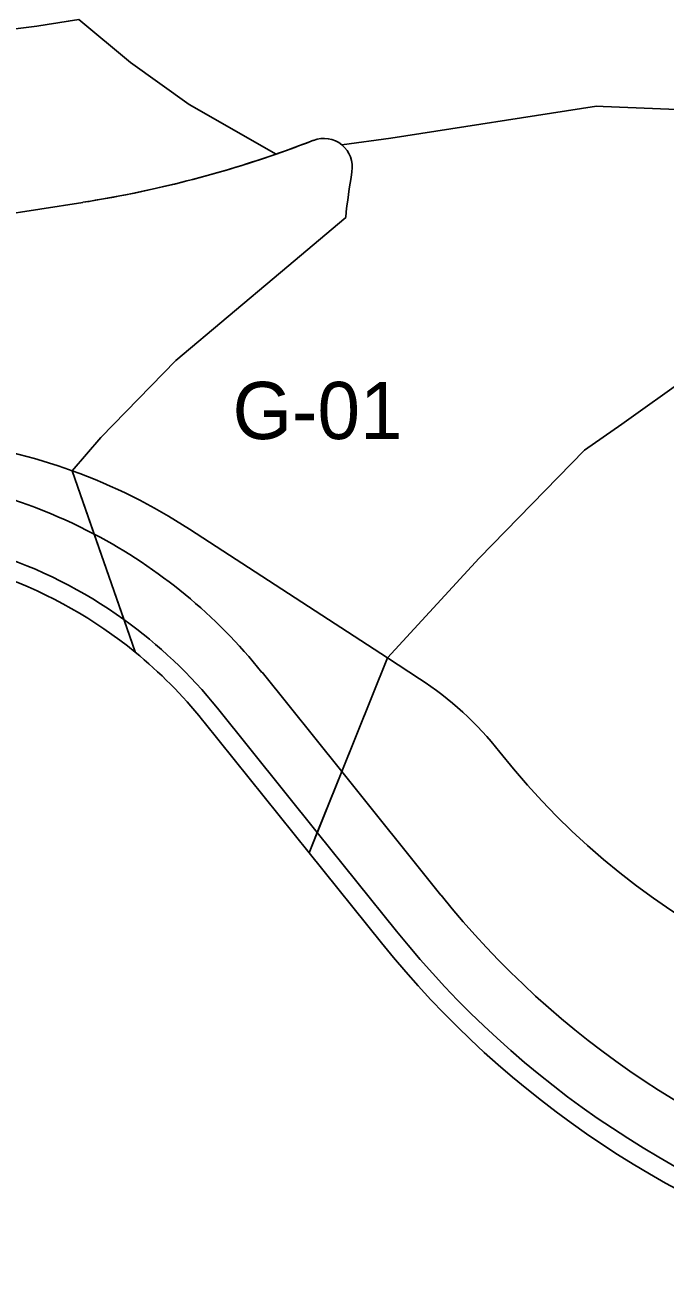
# Model space of a CAD drawing. Extents: x 5196716 to 5200291, y 3709146 to 3713154.
# Drawn here: x 5197340.6 to 5197407.8, y 3709241.5 to 3709372.1 of the extents above; entities that cross this region are included whole.
import ezdxf

# ---------------------------------------------------------------- set-up
doc = ezdxf.new("R2010")
doc.units = 0
for name, color, linetype in [('Drainage-Area', 7, 'Continuous'), ('dsnTextNote', 7, 'Continuous'), ('Level 1', 7, 'Continuous'), ('Level 2', 7, 'Continuous'), ('Level 4', 7, 'Continuous')]:
    doc.layers.add(name, color=color, linetype=linetype)

msp = doc.modelspace()

# ---------------------------------------------------------------- linework, layer by layer
at = {"layer": 'Drainage-Area'}
msp.add_lwpolyline([(5197366.96, 3709358.52), (5197357.83, 3709363.71), (5197351.66, 3709368.11), (5197346.24, 3709372.65)], dxfattribs=at)
at = {"layer": 'Level 1'}
for p, q in [((5197378.98, 3709360.18), (5197400.56, 3709363.54)), ((5197401.27, 3709363.5), (5197400.56, 3709363.54)), ((5197400.56, 3709363.54), (5197401.27, 3709363.5)), ((5197414.02, 3709363.01), (5197401.27, 3709363.5)), ((5197401.27, 3709363.5), (5197414.02, 3709363.01)), ((5197373.85, 3709359.48), (5197378.98, 3709360.18)), ((5197346.68, 3709353.45), (5197325, 3709350.07)), ((5197330.45, 3709350.92), (5197346.68, 3709353.45)), ((5197374.25, 3709351.87), (5197367.41, 3709346.1)), ((5197367.41, 3709346.1), (5197374.25, 3709351.87)), ((5197367.41, 3709346.1), (5197356.44, 3709336.84)), ((5197356.44, 3709336.84), (5197367.41, 3709346.1)), ((5197356.44, 3709336.84), (5197348.55, 3709328.76)), ((5197348.55, 3709328.76), (5197356.44, 3709336.84)), ((5197403.22, 3709330.19), (5197410.2, 3709335.15)), ((5197410.2, 3709335.15), (5197403.22, 3709330.19)), ((5197399.31, 3709327.43), (5197403.22, 3709330.19)), ((5197403.22, 3709330.19), (5197399.31, 3709327.43)), ((5197348.55, 3709328.76), (5197345.54, 3709325.29)), ((5197345.54, 3709325.29), (5197348.55, 3709328.76)), ((5197388.25, 3709316.13), (5197399.31, 3709327.43)), ((5197399.31, 3709327.43), (5197388.25, 3709316.13)), ((5197345.54, 3709325.29), (5197352.15, 3709306.27)), ((5197352.15, 3709306.27), (5197345.54, 3709325.29)), ((5197378.63, 3709305.65), (5197388.25, 3709316.13)), ((5197388.25, 3709316.13), (5197378.63, 3709305.65)), ((5197370.41, 3709285.21), (5197378.63, 3709305.65)), ((5197378.63, 3709305.65), (5197370.41, 3709285.21)), ((5197359.23, 3709299.13), (5197359.4, 3709298.92)), ((5197359.4, 3709298.92), (5197370.41, 3709285.21)), ((5197370.41, 3709285.21), (5197378.01, 3709275.74))]:
    msp.add_line(p, q, dxfattribs=at)
for points in [[(5197366.96, 3709358.52), (5197357.83, 3709363.71), (5197351.66, 3709368.11), (5197346.24, 3709372.65)], [(5197346.24, 3709372.65), (5197351.66, 3709368.11), (5197357.83, 3709363.71), (5197366.96, 3709358.52)], [(5197400.56, 3709363.54), (5197378.98, 3709360.18), (5197373.85, 3709359.48)]]:
    msp.add_lwpolyline(points, dxfattribs=at)
for centre, radius, start, end in [((5197328.7, 3709468.56), 116.5, 278.8769, 291.2212), ((5197328.7, 3709468.56), 116.5, 289.1719, 291.2212), ((5197371.95, 3709357.16), 3, 50.7986, 111.2212), ((5197371.95, 3709357.16), 3, 50.7986, 111.2212), ((5197371.95, 3709357.16), 3, 350.376, 50.7986), ((5197371.95, 3709357.16), 3, 350.376, 50.7986), ((5197328.7, 3709468.56), 116.5, 278.8769, 289.1719), ((5197451.32, 3709343.7), 77.5, 170.376, 173.947), ((5197451.32, 3709343.7), 77.5, 170.376, 173.947), ((5197321.8, 3709269.07), 48, 50.7893, 89.4347), ((5197321.8, 3709269.07), 48, 38.7641, 50.7893), ((5197457.55, 3709339.6), 102, 218.7641, 254.0813)]:
    msp.add_arc(centre, radius, start, end, dxfattribs=at)
at = {"layer": 'Level 2'}
for p, q in [((5197351.66, 3709368.11), (5197346.24, 3709372.65)), ((5197357.83, 3709363.71), (5197351.66, 3709368.11)), ((5197366.96, 3709358.52), (5197357.83, 3709363.71)), ((5197378.98, 3709360.18), (5197400.56, 3709363.54)), ((5197400.56, 3709363.54), (5197401.27, 3709363.5)), ((5197401.27, 3709363.5), (5197400.56, 3709363.54)), ((5197401.27, 3709363.5), (5197414.02, 3709363.01)), ((5197414.02, 3709363.01), (5197401.27, 3709363.5)), ((5197373.85, 3709359.48), (5197378.98, 3709360.18)), ((5197330.45, 3709350.92), (5197346.68, 3709353.45)), ((5197346.68, 3709353.45), (5197330.45, 3709350.92)), ((5197374.25, 3709351.87), (5197367.41, 3709346.1)), ((5197367.41, 3709346.1), (5197374.25, 3709351.87)), ((5197367.41, 3709346.1), (5197356.44, 3709336.84)), ((5197356.44, 3709336.84), (5197367.41, 3709346.1)), ((5197356.44, 3709336.84), (5197348.55, 3709328.76)), ((5197348.55, 3709328.76), (5197356.44, 3709336.84)), ((5197410.2, 3709335.15), (5197403.22, 3709330.19)), ((5197403.22, 3709330.19), (5197410.2, 3709335.15)), ((5197403.22, 3709330.19), (5197399.31, 3709327.43)), ((5197399.31, 3709327.43), (5197403.22, 3709330.19)), ((5197348.55, 3709328.76), (5197345.54, 3709325.29)), ((5197345.54, 3709325.29), (5197348.55, 3709328.76)), ((5197399.31, 3709327.43), (5197388.25, 3709316.13)), ((5197388.25, 3709316.13), (5197399.31, 3709327.43)), ((5197357.86, 3709319.16), (5197378.63, 3709305.65)), ((5197347.85, 3709318.65), (5197350.96, 3709309.7)), ((5197350.96, 3709309.7), (5197347.85, 3709318.65)), ((5197388.25, 3709316.13), (5197378.63, 3709305.65)), ((5197378.63, 3709305.65), (5197388.25, 3709316.13)), ((5197378.63, 3709305.65), (5197382.01, 3709303.45)), ((5197373.83, 3709293.72), (5197365.47, 3709304.14)), ((5197360.79, 3709300.38), (5197371.26, 3709287.34)), ((5197373.83, 3709293.72), (5197371.26, 3709287.34)), ((5197371.26, 3709287.34), (5197373.83, 3709293.72)), ((5197384.25, 3709280.74), (5197373.83, 3709293.72)), ((5197371.26, 3709287.34), (5197379.57, 3709276.99))]:
    msp.add_line(p, q, dxfattribs=at)
for points in [[(5197346.24, 3709372.65), (5197351.66, 3709368.11), (5197357.83, 3709363.71), (5197366.96, 3709358.52)], [(5197400.56, 3709363.54), (5197378.98, 3709360.18), (5197373.85, 3709359.48)]]:
    msp.add_lwpolyline(points, dxfattribs=at)
for centre, radius, start, end in [((5197328.7, 3709468.56), 97.5, 269.8354, 280.3656), ((5197328.7, 3709468.56), 116.5, 278.8769, 291.2212), ((5197328.7, 3709468.56), 116.5, 289.1719, 291.2212), ((5197371.95, 3709357.16), 3, 50.7986, 111.2212), ((5197371.95, 3709357.16), 3, 50.7986, 111.2212), ((5197371.95, 3709357.16), 3, 350.376, 50.7986), ((5197371.95, 3709357.16), 3, 350.376, 50.7986), ((5197328.7, 3709468.56), 116.5, 278.8769, 289.1719), ((5197451.32, 3709343.7), 77.5, 170.376, 173.947), ((5197451.32, 3709343.7), 77.5, 170.376, 173.947), ((5197325.15, 3709268.86), 60, 70.1272, 82.8549), ((5197321.8, 3709269.07), 56, 62.2868, 89.8345), ((5197325.15, 3709268.86), 60, 56.9614, 70.1272), ((5197321.8, 3709269.07), 50, 54.334, 89.8345), ((5197321.8, 3709269.07), 56, 38.7641, 62.2868), ((5197321.8, 3709269.07), 50, 38.7641, 54.334), ((5197362.93, 3709274.11), 35, 38.2119, 56.9614), ((5197451.32, 3709343.7), 77.5, 218.2119, 270.8019), ((5197457.55, 3709339.6), 94, 218.7641, 254.0813), ((5197457.55, 3709339.6), 100, 218.7641, 254.0813)]:
    msp.add_arc(centre, radius, start, end, dxfattribs=at)
at = {"layer": 'Level 4'}
for p, q in [((5197345.54, 3709325.29), (5197347.85, 3709318.65)), ((5197347.85, 3709318.65), (5197345.54, 3709325.29)), ((5197378.63, 3709305.65), (5197357.86, 3709319.16)), ((5197350.96, 3709309.7), (5197352.15, 3709306.27)), ((5197352.15, 3709306.27), (5197350.96, 3709309.7)), ((5197378.63, 3709305.65), (5197373.83, 3709293.72)), ((5197373.83, 3709293.72), (5197378.63, 3709305.65)), ((5197382.01, 3709303.45), (5197378.63, 3709305.65)), ((5197365.47, 3709304.14), (5197373.83, 3709293.72)), ((5197371.26, 3709287.34), (5197360.79, 3709300.38)), ((5197359.23, 3709299.13), (5197359.4, 3709298.92)), ((5197359.4, 3709298.92), (5197370.41, 3709285.21)), ((5197373.83, 3709293.72), (5197384.25, 3709280.74)), ((5197371.26, 3709287.34), (5197370.41, 3709285.21)), ((5197370.41, 3709285.21), (5197371.26, 3709287.34)), ((5197379.57, 3709276.99), (5197371.26, 3709287.34)), ((5197370.41, 3709285.21), (5197378.01, 3709275.74))]:
    msp.add_line(p, q, dxfattribs=at)
for centre, radius, start, end in [((5197328.7, 3709468.56), 97.5, 269.8354, 280.3656), ((5197325.15, 3709268.86), 60, 70.1272, 82.8549), ((5197321.8, 3709269.07), 56, 62.2868, 89.8345), ((5197325.15, 3709268.86), 60, 56.9614, 70.1272), ((5197321.8, 3709269.07), 50, 54.334, 89.8345), ((5197321.8, 3709269.07), 56, 38.7641, 62.2868), ((5197321.8, 3709269.07), 48, 50.7893, 89.4347), ((5197321.8, 3709269.07), 50, 38.7641, 54.334), ((5197321.8, 3709269.07), 48, 38.7641, 50.7893), ((5197362.93, 3709274.11), 35, 38.2119, 56.9614), ((5197451.32, 3709343.7), 77.5, 218.2119, 270.8019), ((5197457.55, 3709339.6), 94, 218.7641, 254.0813), ((5197457.55, 3709339.6), 100, 218.7641, 254.0813), ((5197457.55, 3709339.6), 102, 218.7641, 254.0813)]:
    msp.add_arc(centre, radius, start, end, dxfattribs=at)

# ---------------------------------------------------------------- texts
at = {"layer": 'dsnTextNote'}
msp.add_text('G-01', height=6, dxfattribs=at).set_placement((5197362.38, 3709328.61))

doc.saveas('drawing.dxf')
